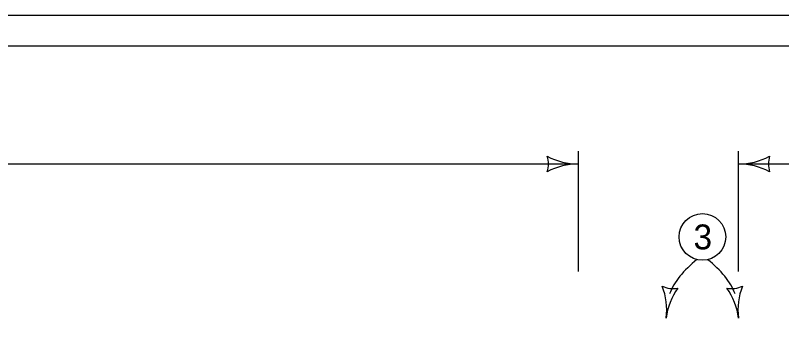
# Model space of a CAD drawing. Extents: x 8045 to 81668, y 6217 to 16762.
# Drawn here: x 11036 to 11528.5, y 9745.2 to 9944 of the extents above; entities that cross this region are included whole.
import ezdxf

# ---------------------------------------------------------------- set-up
doc = ezdxf.new("R2010")
doc.units = 0
for name, color, linetype in [('dsnCellElements', 7, 'Continuous'), ('dsnStdDimension', 7, 'Continuous'), ('dsnStdSection', 7, 'Continuous'), ('Level 8', 7, 'Continuous')]:
    doc.layers.add(name, color=color, linetype=linetype)

msp = doc.modelspace()

# ---------------------------------------------------------------- linework, layer by layer
at = {"layer": 'dsnCellElements'}
for p, q in [((11397.86, 9779.31), (11397.86, 9856.7)), ((11397.86, 9779.31), (11397.86, 9856.7)), ((11500.75, 9779.31), (11500.75, 9856.7)), ((11500.75, 9779.31), (11500.75, 9856.7)), ((10375.45, 9848.49), (11397.86, 9848.49)), ((10375.45, 9848.49), (11397.86, 9848.49)), ((11500.75, 9848.49), (11805.49, 9848.49))]:
    msp.add_line(p, q, dxfattribs=at)
for centre, radius, start, end in [((11362.23, 9848.49), 16.42, 342.2666, 17.7333), ((11397.86, 9890.99), 42.5, 241.9275, 270), ((11362.23, 9848.49), 16.42, 342.2666, 17.7333), ((11397.86, 9890.99), 42.5, 241.9275, 270), ((11500.75, 9890.99), 42.5, 270, 298.0725), ((11500.75, 9890.99), 42.5, 270, 298.0725), ((11536.39, 9848.49), 16.42, 162.2666, 197.7334), ((11536.39, 9848.49), 16.42, 162.2666, 197.7334), ((11397.86, 9805.99), 42.5, 90, 118.0725), ((11397.86, 9805.99), 42.5, 90, 118.0725), ((11500.75, 9805.99), 42.5, 61.9275, 90), ((11500.75, 9805.99), 42.5, 61.9275, 90)]:
    msp.add_arc(centre, radius, start, end, dxfattribs=at)
at = {"layer": 'dsnStdDimension'}
msp.add_line((10152.18, 9924.36), (13247.87, 9924.36), dxfattribs=at)
at = {"layer": 'dsnStdSection'}
msp.add_lwpolyline([(10132.52, 9944.02), (13267.53, 9944.02), (13267.53, 7924.02), (10132.52, 7924.02)], close=True, dxfattribs=at)
at = {"layer": 'Level 8'}
msp.add_circle((11477.56, 9801.62), 15, dxfattribs=at)
for centre, radius, start, end in [((11458.66, 9784.88), 16.42, 245.1764, 280.6431), ((11412.09, 9754.76), 42.5, 352.9098, 20.9823), ((11496.44, 9744.27), 42.5, 144.8373, 172.9098), ((11496.35, 9784.88), 16.42, 259.3569, 294.8236), ((11458.57, 9744.27), 42.5, 7.0902, 35.1627), ((11542.92, 9754.76), 42.5, 159.0177, 187.0902)]:
    msp.add_arc(centre, radius, start, end, dxfattribs=at)
for centre, major_axis, start_param, end_param in [((11543.41, 9761.85), (-89.15, -12.34), 5.523141, 5.97728), ((11411.6, 9761.85), (89.15, -12.34), 0.305948, 0.759638)]:
    msp.add_ellipse(centre, major_axis=major_axis, ratio=0.555556, start_param=start_param, end_param=end_param, dxfattribs=at)

# ---------------------------------------------------------------- texts
msp.add_text('3', height=16, dxfattribs=at).set_placement((11471.85, 9793.62))

doc.saveas('drawing.dxf')
